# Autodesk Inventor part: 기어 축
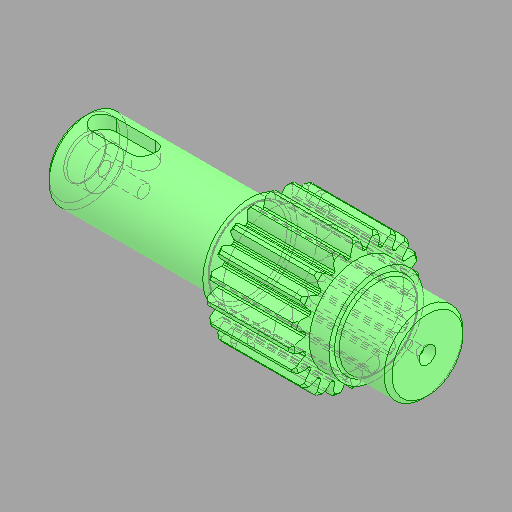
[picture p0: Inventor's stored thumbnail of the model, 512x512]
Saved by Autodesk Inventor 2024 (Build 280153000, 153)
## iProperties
Created: 2025-11
Part Number: 기어 축
Material: 강철, 합금
Document SubType Name: Modeling
Designer: Edu09
Density: 7.73 g/cm^3
Appearance: 기본값
Author: jhkim
Sending System: Autodesk Inventor 2026
Preprocessor: ST-DEVELOPER v20.1
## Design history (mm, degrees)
feature "솔리드1"
node "솔리드2"
